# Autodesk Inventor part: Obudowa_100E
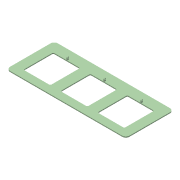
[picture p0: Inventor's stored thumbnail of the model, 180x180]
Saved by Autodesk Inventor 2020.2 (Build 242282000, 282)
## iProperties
Created: 2005-10
Part Number: Obudowa_100E
Document SubType Name: Modeling
Designer: F.Stasiak
Density: 1 g/cm^3
Material: Ogólny
Appearance: Zielony pastelowy
Manager: www.cadconsulting.pl
Company: Fabian Stasiak CAD Consulting
Author: F.Stasiak
Subject: Zbiór ćwiczeń. Autodesk Inventor 2020. Kurs podstawowy
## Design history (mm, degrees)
sketch "Szkic1"
  geometry: L1 (500, 400)-(-500, 400); L2 (-500, 400)-(-500, 0); L3 (-500, 0)-(500, 0); L4 (500, 0)-(500, 400); 2 further points
  constraints: 8 end point, 2 parallel, 1 coincident, 1 horizontal, 1 midpoint, 1 perpendicular, 1 other
  dimensions: "d0" = 1000 distance of L2.end L3.end; "d1" = 400 distance of L1.end L2.end
extrude "Wyciągnięcie proste1" new body sketch "Szkic1" distance "d2" = 8; taper "d3" = 0 deg
sketch "Szkic2"
  geometry: L1 (-500, 400)-(500, 400) reference; L2 (-500, 0)-(-500, 400) reference; L3 (500, 0)-(-500, 0) reference; L4 (500, 400)-(500, 0) reference; L5 (-112.5, 314.834)-(112.5, 314.834); L6 (112.5, 314.834)-(112.5, 64.834); L7 (112.5, 64.834)-(-112.5, 64.834); L8 (-112.5, 64.834)-(-112.5, 314.834); L9 (0, 400)-(0, 0); 1 further point
  constraints: 10 end point, 3 midpoint, 2 parallel, 1 horizontal, 1 perpendicular, 1 point on line
  dimensions: "d4" = 225 distance of L6.end L7.end; "d5" = 250 distance of L5.end L6.end
extrude "Wyciągnięcie proste2" cut sketch "Szkic2" extent not by distance; stored distance "d6" = 5; taper "d7" = 0 deg
fillet "Zaokrąglenie1" dims "d8" = 10
node "Płaszczyzna konstrukcyjna1"
sketch "Szkic4"
  geometry: L1 (400, 0)-(314.834, 0); L2 (334.834, 0)-(334.834, -12); L3 (354.834, -12)-(354.834, 0); L4 (334.834, 0)-(354.834, 0); C1 r 5 at (344.834, -12); A1 r 10 centre (344.834, -12) between (334.834, -12) and (354.834, -12)
  constraints: 8 end point, 2 centre point, 2 perpendicular, 2 point on circle, 2 point on line, 2 tangent, 1 coincident, 1 horizontal, 1 parallel
  dimensions: "d10" = 10 radius of A1; "d11" = 12 distance of L3.start L3.end; "d12" = 20 distance from line of L2 L1.end; "d13" = 10 diameter of C1
extrude "Wyciągnięcie proste3" join sketch "Szkic4" stored distance "d14" = 8; taper "d15" = 0 deg
mirror "Lustro1"
sketch "Szkic5"
  geometry: L1 (0, 8)-(400, 8) reference; L2 (330.834, 8)-(330.834, 23); L3 (314.834, 23)-(314.834, 8); L4 (314.834, 8)-(330.834, 8); C1 r 5 at (322.834, 23); A1 r 8 centre (322.834, 23) between (330.834, 23) and (314.834, 23); 1 further point
  constraints: 6 end point, 2 centre point, 2 perpendicular, 2 point on circle, 2 tangent, 1 coincident, 1 collinear, 1 parallel, 1 point on line
  dimensions: "d16" = 10 diameter of C1; "d17" = 8 radius of A1; "d18" = 15 distance of L3.start L3.end
extrude "Wyciągnięcie proste4" join sketch "Szkic5" stored distance "d19" = 8; taper "d20" = 0 deg
pattern_linear "Szyk prostokątny1"
fillet "Zaokrąglenie2" dims "d27" = 30
node "Bryła1"
node "Korpusy bryłowe"
node "Korpusy powierzchniowe"
node "Pętla rzutowana1"
